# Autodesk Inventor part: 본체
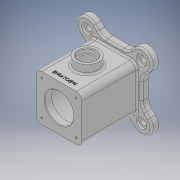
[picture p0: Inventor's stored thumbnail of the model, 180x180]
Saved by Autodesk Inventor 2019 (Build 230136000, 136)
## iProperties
Created: 2021-01
Part Number: 본체
Material: 일반
Document SubType Name: Modeling
Designer: 3DPRO17
Density: 1 g/cm^3
Appearance: 기본값
Author: 3DPRO17
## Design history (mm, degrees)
sketch "스케치2"
  geometry: L1 (48, 48)-(-48, 48); L2 (-48, 48)-(-48, -48); L3 (-48, -48)-(48, -48); L4 (48, -48)-(48, 48); L5 (48, 48)-(-48, -48); L6 (-48, 48)-(48, -48); 1 further point
  constraints: 12 end point, 2 midpoint, 2 parallel, 1 horizontal, 1 perpendicular
  dimensions: "d16" = 96 distance of L3.end L2.end; "d17" = 96 distance of L2.end L1.end
extrude "돌출1" new body sketch "스케치2" distance "d18" = 12; taper "d19" = 0 deg
sketch "스케치3"
  geometry: L1 (-40, -40)-(40, -40); L2 (40, -40)-(40, 40); L3 (40, 40)-(-40, 40); L4 (-40, 40)-(-40, -40); L5 (-40, -40)-(40, 40); L6 (40, -40)-(-40, 40); 1 further point
  constraints: 12 end point, 2 midpoint, 2 parallel, 1 horizontal, 1 perpendicular
  dimensions: "d20" = 80 distance of L3.end L2.end; "d21" = 80 distance of L2.end L1.end
extrude "돌출2" join sketch "스케치3" distance "d22" = 96; taper "d23" = 0 deg
sketch "스케치4"
  geometry: L1 (-48, 48)-(48, 48) reference; L2 (-48, -48)-(-48, 48) reference; L3 (48, -48)-(-48, -48) reference; L4 (48, 48)-(48, -48) reference; L5 (-47.376, -47.376)-(0, 0); L6 (0, 0)-(47.376, -47.376); L7 (0, 0)-(-47.376, 47.376); L8 (0, 0)-(47.376, 47.376); C1 r 18 at (47.376, -47.376); C2 r 18 at (-47.376, -47.376); C3 r 18 at (47.376, 47.376); C4 r 18 at (-47.376, 47.376); A1 r 67 centre (0, 0) between (47.376, -47.376) and (-47.376, -47.376); 1 further point
  constraints: 8 end point, 5 centre point, 4 point on circle, 2 horizontal alignment, 1 coincident
  dimensions: "d24" = 134 diameter of A1; "d25" = 36 diameter of C1; "d26" = 36 diameter of C2; "d28" = 36 diameter of C3; "d29" = 36 diameter of C4; "d100" = 45 deg angle of L4 L8; "d101" = 45 deg angle of L5 L2
extrude "돌출3" join sketch "스케치4" distance "d31" = 12; taper "d32" = 0 deg
sketch "스케치5"
  geometry: C1 r 25 at (0, 0); 1 further point
  constraints: 1 centre point, 1 coincident
  dimensions: "d34" = 50 diameter of C1
extrude "돌출4" cut sketch "스케치5" stored distance "d35" = 50 (= d34); taper "d36" = 0 deg
node "작업 평면2"
sketch "스케치8"
  geometry: C1 r 35 at (0, 0); 1 further point
  constraints: 1 centre point, 1 coincident
  dimensions: "d42" = 70 diameter of C1
extrude "돌출6" cut sketch "스케치8" distance "d43" = 84; taper "d44" = 0 deg
sketch "스케치9"
  geometry: L1 (10.613, -12)-(69.387, -12) reference; C1 r 20 at (40, 47); 4 further points
  constraints: 1 centre point, 1 midpoint, 1 vertical alignment
  dimensions: "d45" = 40 diameter of C1; "d46" = 59 distance from line of C1.centre L1
extrude "돌출7" join sketch "스케치9" distance "d47" = 15; taper "d48" = 0 deg
sketch "스케치10"
  geometry: C1 r 20 at (0, 0) reference; 2 further points
  constraints: 1 coincident
hole "구멍1" sketch "스케치10" at (0, 0) diameter "d49" = 25; stored, may be unused: countersink angle "d53" = 90 deg, drill point angle "d55" = 0 deg; dims "d50" = 8, "d51" = 30, "d52" = 8, "d54" = 10
sketch "스케치12"
  geometry: C1 r 9 at (-47.376, 47.376); C2 r 5 at (-47.376, 47.376); A1 r 18 centre (-47.376, 47.376) between (-29.387, 48) and (-48, 29.387) reference; 3 further points
  constraints: 2 centre point, 2 concentric
  dimensions: "d62" = 18 diameter of C1; "d63" = 10 diameter of C2
extrude "돌출9" cut sketch "스케치12" stored distance "d64" = 15; taper "d65" = 0 deg
extrude "돌출10" cut sketch "스케치12" distance "d66" = 4; taper "d67" = 0 deg
sketch "스케치13"
  geometry: L1 (30, -30)-(-30, -30); L2 (-30, -30)-(-30, 30); L3 (-30, 30)-(30, 30); L4 (30, 30)-(30, -30); L5 (30, -30)-(-30, 30); L6 (-30, -30)-(30, 30); 5 further points
  constraints: 12 end point, 4 coincident, 2 midpoint, 2 parallel, 1 horizontal, 1 perpendicular
  dimensions: "d68" = 60 distance of L2.end L3.end; "d69" = 60 distance of L1.end L2.end
hole "구멍2" sketch "스케치13" at (-30, -30), (-30, 30), (30, 30), (30, -30) diameter "d70" = 3.242; stored, may be unused: countersink angle "d74" = 90 deg, drill point angle "d76" = 118 deg; dims "d71" = 8, "d72" = 30, "d73" = 8, "d75" = 10
sketch "스케치14"
  geometry: L1 (-30, 30)-(30, 30); L2 (30, 30)-(30, -30); L3 (30, -30)-(-30, -30); L4 (-30, -30)-(-30, 30); L5 (-30, 30)-(30, -30); L6 (30, 30)-(-30, -30); C1 r 1.621 at (30, -30) reference; 5 further points
  constraints: 12 end point, 4 coincident, 2 midpoint, 2 parallel, 1 horizontal, 1 perpendicular
  dimensions: "d77" = 60 distance of L2.end L3.end; "d78" = 60 distance of L1.end L2.end
hole "구멍3" sketch "스케치14" at (30, 30), (30, -30), (-30, -30), (-30, 30) diameter "d79" = 3.242; stored, may be unused: countersink angle "d83" = 90 deg, drill point angle "d85" = 118 deg; dims "d80" = 8, "d81" = 30, "d82" = 8, "d84" = 10
sketch "스케치15"
  geometry: L1 (0, 96)-(80, 96) reference; C1 r 20 at (40, 47) reference; 2 further points
  constraints: 1 vertical alignment, 1 other
  dimensions: "d86" = 10 distance from line of point (40, 86) L1
feature "엠보싱1" sketch "스케치15" dims "d16" = 96, "d17" = 96, "d24" = 134, "d25" = 36, "d26" = 36, "d28" = 36, "d29" = 36, "d87" = 0.5, "d88" = 0, "d100" = 45 deg, "d101" = 45 deg
fillet "모깎기2" dims "d89" = 10
chamfer "모따기1" distance "d90" = 1; stored, may be unused: second distance "d91" = 2, angle "d92" = 45 deg
fillet "모깎기5" dims "d95" = 3
chamfer "모따기2" distance "d96" = 1; stored, may be unused: second distance "d97" = 2, angle "d98" = 45 deg
sketch "스케치16"
  geometry: L1 (-48, 29.387)-(-48, -29.387) reference; L2 (0, 0)-(-47.376, 47.376); L3 (-48, 22.544)-(-60.104, 34.648); L4 (-22.544, 48)-(-34.648, 60.104); L5 (29.387, 48)-(-29.387, 48) reference; L6 (-48, 22.544)-(-48, 29.387); L7 (-29.387, 48)-(-22.544, 48); A1 r 18 centre (-47.376, 47.376) between (-29.387, 48) and (-48, 29.387) reference; A2 r 18 centre (-47.376, 47.376) between (-29.387, 48) and (-34.648, 60.104); A3 r 18 centre (-47.376, 47.376) between (-60.104, 34.648) and (-48, 29.387)
  constraints: 10 end point, 4 point on circle, 3 point on line, 2 centre point, 2 parallel, 2 tangent, 1 coincident, 1 collinear, 1 concentric, 1 perpendicular
extrude "돌출11" join sketch "스케치16" distance "d102" = 12; taper "d103" = 0 deg
fillet "모깎기6" dims "d107" = 20
fillet "모깎기7" dims "d108" = 3
node "솔리드1"
mirror "미러1"
mirror "미러2"
pattern_circular "원형 패턴1" dims angle "d105" = 360 deg
node "투영된 루프1"
other parameters: "d2" = 134, "d41" = 12
